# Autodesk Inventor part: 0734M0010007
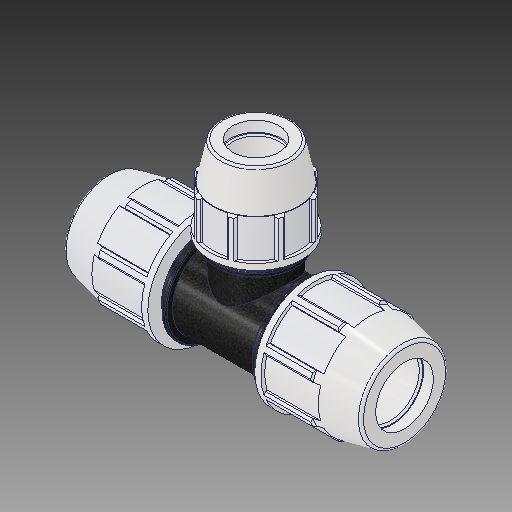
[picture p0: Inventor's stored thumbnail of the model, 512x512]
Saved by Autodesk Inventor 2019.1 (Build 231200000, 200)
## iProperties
Created: 2017-02
Part Number: 0734M0010007
Material: PVC-Piping
Description: PLASSON REDUCING TEE 1'' - 3/4'' - 1''
Document SubType Name: Modeling
Designer: KIM
Mass: 92.6774 g
Surface Area: 199.44 cm^2
Volume: 66.1981 cm^3
Density: 1.4 g/cm^3
Appearance: PTFE
Author: Кирилл
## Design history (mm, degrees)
derived "0734M0.ipt"
feature "Solid1::0734M0.ipt"
feature "Solid2::0734M0.ipt"
tag "TaggingFeature1"
body "Solid1"
other parameters: "d2" = 33.3, "d4" = 7.12258, "d5" = 23.93188, "d7" = 62.992, "d11" = 2.84903, "d13" = 120 deg, "d14" = 49.95, "d15" = 12 deg, "d16" = 54.80304, "d18" = 1.665, "d19" = 35 deg, "d20" = 17.5 deg, "d21" = 58.58256, "d23" = 0, "d25" = 360 deg, "d27" = 1.25984, "d33" = 0.666, "d42" = 30.76956, "d43" = 1.88976, "d46" = 0.999, "d67" = 47.244, "d76" = 26.6, "d77" = 53.086, "d78" = 12 deg, "d79" = 85.09, "d80" = 120 deg, "d81" = 39.9, "d82" = 7.09083, "d87" = 2.83633, "d89" = 21.2725, "d90" = 25.527, "d96" = 14.24517, "d98" = 49.36998, "d99" = 35 deg, "d100" = 17.5 deg, "d102" = 0, "d103" = 1.06172, "d107" = 360 deg, "d109" = 0.798, "d112" = 1.33, "d113" = 3.53907, "d114" = 0, "d117" = 170.942, "d118" = 46.18482, "d126" = 29.97, "d127" = 66.04, "d131" = 3.4036, "d132" = 23.94, "d133" = 59.944, "d135" = 0, "d138" = 3.41884, "d143" = 0, "d148" = 39.8145, "d168" = 29.97, "d170" = 0, "d171" = 26.6, "d173" = 0, "d176" = 3.53907, "d177" = 0, "d_" = 33.3, "E_" = 62.992, "A_" = 85.09, "l_" = 66.04, "E_1" = 53.086, "l_1" = 59.944, "d_1" = 26.6, "H_" = 170.942
